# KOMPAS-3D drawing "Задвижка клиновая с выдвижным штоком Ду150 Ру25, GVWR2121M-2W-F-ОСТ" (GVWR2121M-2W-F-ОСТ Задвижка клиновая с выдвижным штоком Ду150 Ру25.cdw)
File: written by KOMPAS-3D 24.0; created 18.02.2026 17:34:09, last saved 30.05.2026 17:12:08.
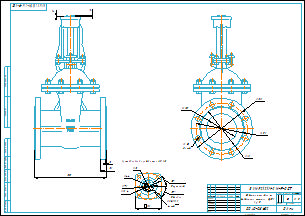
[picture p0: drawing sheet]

Document properties: art: D040-10013; Автор: R2D2; Форматы листов документа: A2; Полное имя файла: GVWR2121M-2W-F-ОСТ Задвижка клиновая с выдвижным штоком Ду150 Ру25.m3d; Масса: 60; Наименование: Задвижка клиновая с выдвижным штоком Ду150 Ру25; Количество листов документа: 1; Примечание: D040-08602

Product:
- Component [detail]: ANSI B18.2.4.2M - M16x2 - 24  | designation ANSI B18.2.4.2M - M16x2  | qty 8  | pos. 2  | Комментарий: Типы метрических   шестигранных гаек   2; Автор: R2D2; additional columns: Сталь, мягкая; source file: ..\ANSI B18.2.4.2M - M16x2 ANSI B18.2.4.2M - M16x2 - 24.m3d
- Component [detail]: AS 1110 - M16 x 60  | qty 8  | pos. 3  | Комментарий: Болты и винты   шестигранные точные   метрические ISO; Автор: R2D2; additional columns: Сталь, мягкая; source file: ..\AS 1110 - M16 x 60 AS 1110 - M16 x 60.m3d
- Component [detail]: AS 1110 - M10 x 35  | qty 4  | pos. 4  | Комментарий: Болты и винты   шестигранные точные   метрические ISO; Автор: R2D2; additional columns: Сталь, мягкая; source file: ..\AS 1110 - M10 x 35 AS 1110 - M10 x 35.m3d
- Component [detail]: ANSI B18.2.4.2M - M10x1,5 - 16  | designation ANSI B18.2.4.2M - M10x1,5  | qty 4  | pos. 5  | Комментарий: Типы метрических   шестигранных гаек   2; Автор: R2D2; additional columns: Сталь, мягкая; source file: ..\ANSI B18.2.4.2M - M10x1,5 ANSI B18.2.4.2M - M10x1,5 - 16.m3d
- Component [detail]: ANSI B18.2.4.2M - M8x1,25 - 13  | designation ANSI B18.2.4.2M - M8x1,25  | qty 1  | pos. 6  | Комментарий: Типы метрических   шестигранных гаек   2; Автор: R2D2; additional columns: Сталь, мягкая; source file: ..\ANSI B18.2.4.2M - M8x1,25 ANSI B18.2.4.2M - M8x1,25 - 13.m3d
- Component [detail]: Деталь1  | qty 1  | pos. 7  | Автор: R2D2; additional columns: Типовые; source file: ..\2.m3d
- Component [detail]: Фланец  | qty 1  | pos. 8  | Автор: R2D2; additional columns: Типовые; source file: ..\Фланец DN150 PN25 b30.m3d
- Component [detail]: Фланец  | qty 1  | pos. 9  | Автор: R2D2; additional columns: Типовые; source file: ..\Фланец DN150 PN25 b30.m3d
- Component [detail]: ANSI B18.2.4.2M - M8x1,25 - 13  | designation ANSI B18.2.4.2M - M8x1,25-01  | qty 1  | pos. 6  | Комментарий: Типы метрических   шестигранных гаек   2; Автор: R2D2; additional columns: Сталь, мягкая; source file: ..\ANSI B18.2.4.2M - M8x1,25 ANSI B18.2.4.2M - M8x1,25 - 13.m3d
- Component [assembly]: DN50_3D_STEP  | designation Сборка  | qty 1  | Масса: 2.725126; Автор: R2D2; source file: ..\Фланец А.a3d
- Body: Тело 1  | qty 1
    Масса: 107.979176
- Body: Тело 2  | qty 1
    Масса: 107.979176
- Part/product: Задвижка клиновая с выдвижным штоком Ду150 Ру25  | designation GVWR2121M-2W-F-ОСТ
    Масса: 60
    Раздел спецификации: Прочие изделия
    Примечание: D040-08602
    additional columns: D040-10013

Views: Проекционный вид 3
Referenced files in E:\Работа\Зайцев\Для компаса\: чертеж DN.ru А3.cdt
Referenced files in E:\Работа\Зайцев\GVWR2121M-2W-F-ОСТ Задвижка клиновая 30с964нж DN.ru Ду50-300 Ру25\исходные материалы\DN150\DN150\: GVWR2121M-2W-F-ОСТ Задвижка клиновая с выдвижным штоком Ду150 Ру25.m3d
Referenced files in E:\Работа\Зайцев\GVWR2121M-2W-F-ОСТ Задвижка клиновая 30с964нж DN.ru Ду50-300 Ру25\исходные материалы\DN150\: ANSI B18.2.4.2M - M16x2 ANSI B18.2.4.2M - M16x2 - 24.m3d, AS 1110 - M16 x 60 AS 1110 - M16 x 60.m3d, AS 1110 - M10 x 35 AS 1110 - M10 x 35.m3d, ANSI B18.2.4.2M - M10x1,5 ANSI B18.2.4.2M - M10x1,5 - 16.m3d, ANSI B18.2.4.2M - M8x1,25 ANSI B18.2.4.2M - M8x1,25 - 13.m3d, 2.m3d, Фланец DN150 PN25 b30.m3d, Фланец А.a3d
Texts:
  Присоединение привода тип АК (А)
  чертеж DN.ru А3.cdt
  Задвижка клиновая с
  выдвижным штоком Ду150
  Ру25
  GVWR2121M-2W-F-ОСТ
  Solid1
  ANSI B18.2.4.2M - M16x2 - 24
  ANSI B18.2.4.2M - M16x2
  ANSI B18.2.4.2M - M16x2 ANSI B18.2.4.2M - M16x2 - 24
  AS 1110 - M16 x 60
  AS 1110 - M16 x 60 AS 1110 - M16 x 60
  AS 1110 - M10 x 35
  AS 1110 - M10 x 35 AS 1110 - M10 x 35
  ANSI B18.2.4.2M - M10x1,5 - 16
  ANSI B18.2.4.2M - M10x1,5
  ANSI B18.2.4.2M - M10x1,5 ANSI B18.2.4.2M - M10x1,5 - 16
  ANSI B18.2.4.2M - M8x1,25 - 13
  ANSI B18.2.4.2M - M8x1,25
  ANSI B18.2.4.2M - M8x1,25 ANSI B18.2.4.2M - M8x1,25 - 13
  Твердое тело1
  Деталь1
  Деталь1 Деталь1
  Фланец
  ANSI B18.2.4.2M - M8x1,25-01 ANSI B18.2.4.2M - M8x1,25 - 13
  Сборка
  Сборка DN50_3D_STEP
  Задвижка клиновая с выдвижным штоком Ду150 Ру25
  GVWR2121M-2W-F-ОСТ Задвижка клиновая с выдвижным штоком Ду150 Ру25
Dimensions and other numbers on the sheet: 100; 5 кулачков; 5 впадин; 14(М12); 4 отв.; 104; 70; 44; 32; 1:2,5; 0; 1; 2; 60; 01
